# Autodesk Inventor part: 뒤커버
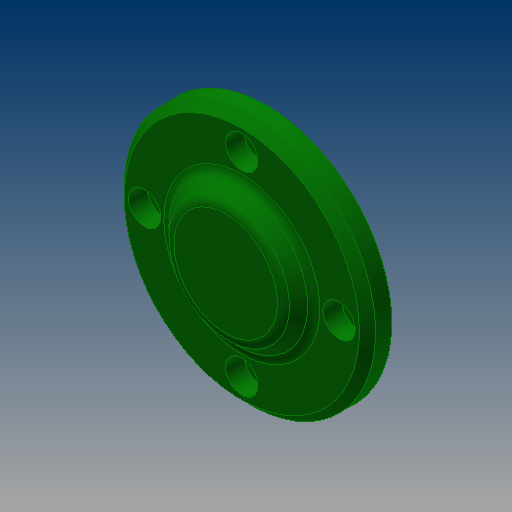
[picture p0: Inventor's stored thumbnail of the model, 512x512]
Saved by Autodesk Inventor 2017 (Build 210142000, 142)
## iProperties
Created: 2015-09
Part Number: 뒤커버
Material: 알루미늄 6061
Document SubType Name: Modeling
Designer: mduedu
Density: 1 g/cm^3
Appearance: 진녹색
Author: mduedu
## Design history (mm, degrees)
sketch "스케치1"
  geometry: L1 (0, 7.5)-(0, -7.5); L2 (0, 7.5)-(14, 7.5); L3 (14, 7.5)-(18, 3.5); L4 (18, 3.5)-(31, 3.5); L5 (31, 3.5)-(31, -2.5); L6 (31, -2.5)-(17.5, -2.5); L7 (17.5, -2.5)-(17.5, -7.5); L8 (17.5, -7.5)-(0, -7.5); 2 further points
  constraints: 16 end point, 3 parallel, 2 perpendicular, 1 coincident, 1 horizontal, 1 midpoint, 1 vertical
  dimensions: "d0" = 15 distance of L1.start L1.end; "d1" = 4 distance between parallel lines of L4 L2; "d2" = 6 distance of L4.end L5.end; "d3" = 36 diameter of L3.end L1; "d4" = 35 diameter of L7 L1; "d5" = 62 diameter of L5 L1; "d7" = 45 deg angle of L3 L5
revolve "회전1" sketch "스케치1" stored, may be unused: angle "d8" = 90 deg
hole "구멍1" diameter "d11" = 24; stored, may be unused: countersink angle "d15" = 90 deg, drill point angle "d17" = 0 deg; dims "d9" = 10, "d10" = 10, "d12" = 6, "d13" = 4, "d14" = 2, "d16" = 8
fillet "모깎기1" dims "d18" = 3
chamfer "모따기2" distance "d22" = 2; stored, may be unused: second distance "d23" = 2, angle "d24" = 45 deg
fillet "모깎기2" dims "d25" = 3
fillet "모깎기3" dims "d26" = 3
sketch "스케치2" dims "d27" = 48
  geometry: 6 further points
  constraints: 2 vertical alignment, 1 coincident, 7 other
  dimensions: "d33" = 360 deg dimension on point (0, 0) point (0, 24) (derived)
sketch "스케치3"
  geometry: 4 further points
hole "구멍2" sketch "스케치3" at (-24, 0), (0, -24), (24, 0), (0, 24) diameter "d35" = 4.5; stored, may be unused: countersink angle "d39" = 90 deg, drill point angle "d41" = 0 deg; dims "d36" = 6, "d37" = 8, "d38" = 4.6, "d40" = 8
chamfer "모따기3" distance "d42" = 1; stored, may be unused: second distance "d43" = 2, angle "d44" = 45 deg
node "솔리드1"
